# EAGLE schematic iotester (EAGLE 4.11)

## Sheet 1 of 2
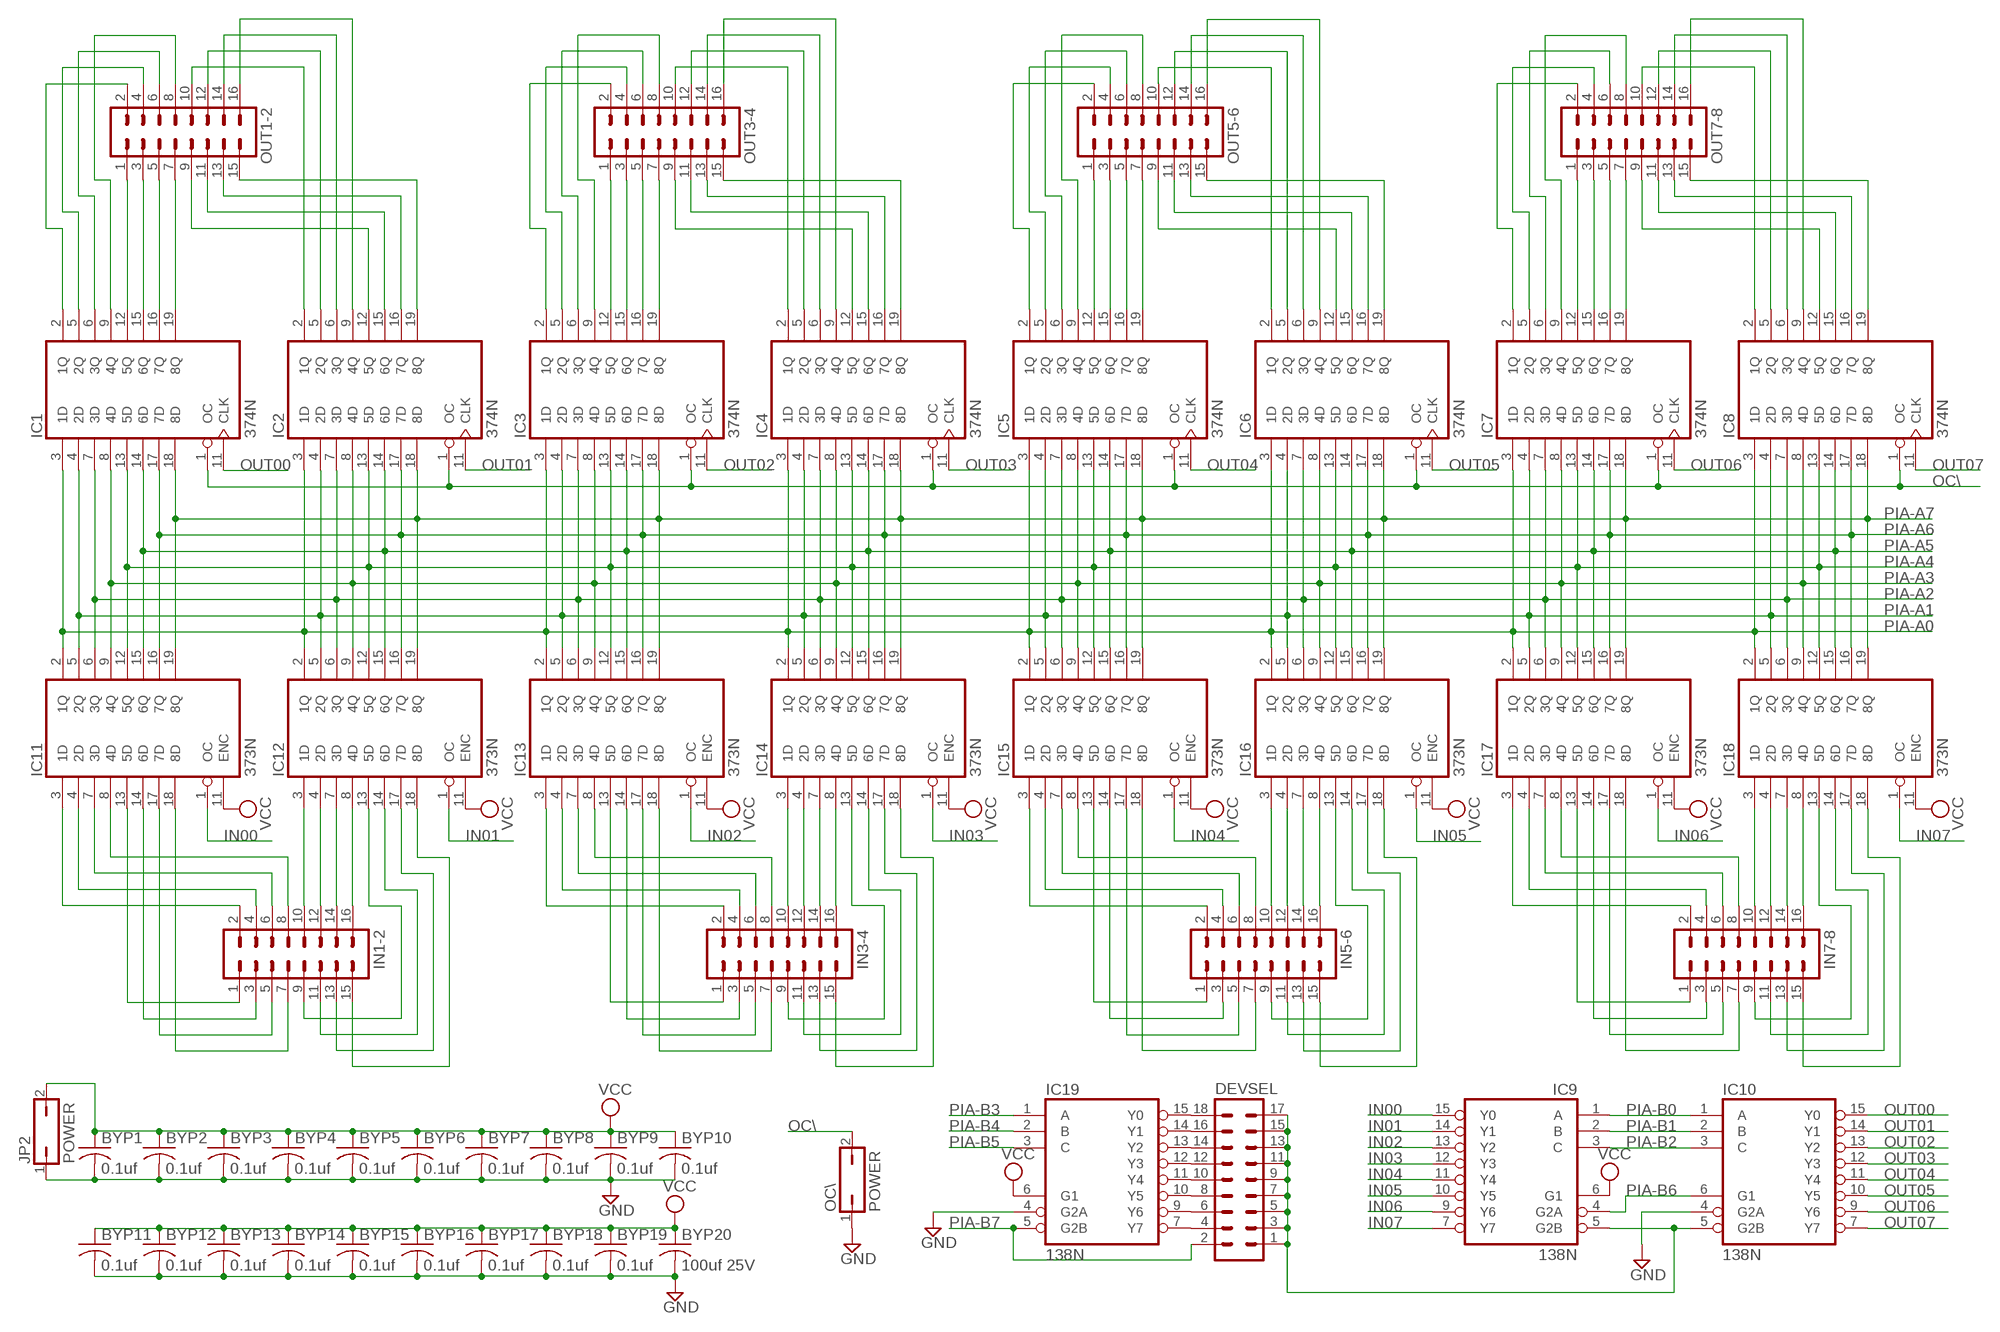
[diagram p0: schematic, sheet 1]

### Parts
BYP1  0.1uf  C-US050-025X075  [C050-025X075]
BYP2  0.1uf  C-US050-025X075  [C050-025X075]
BYP3  0.1uf  C-US050-025X075  [C050-025X075]
BYP4  0.1uf  C-US050-025X075  [C050-025X075]
BYP5  0.1uf  C-US050-025X075  [C050-025X075]
BYP6  0.1uf  C-US050-025X075  [C050-025X075]
BYP7  0.1uf  C-US050-025X075  [C050-025X075]
BYP8  0.1uf  C-US050-025X075  [C050-025X075]
BYP9  0.1uf  C-US050-025X075  [C050-025X075]
BYP10  0.1uf  C-US050-025X075  [C050-025X075]
BYP11  0.1uf  C-US050-025X075  [C050-025X075]
BYP12  0.1uf  C-US050-025X075  [C050-025X075]
BYP13  0.1uf  C-US050-025X075  [C050-025X075]
BYP14  0.1uf  C-US050-025X075  [C050-025X075]
BYP15  0.1uf  C-US050-025X075  [C050-025X075]
BYP16  0.1uf  C-US050-025X075  [C050-025X075]
BYP17  0.1uf  C-US050-025X075  [C050-025X075]
BYP18  0.1uf  C-US050-025X075  [C050-025X075]
BYP19  0.1uf  C-US050-025X075  [C050-025X075]
BYP20  100uf 25V  C-US150-064X183  [C150-064X183]
DEVSEL  MA09-2  [MA09-2]
IC1  374N  74LS374N  [DIL20]
IC2  374N  74LS374N  [DIL20]
IC3  374N  74LS374N  [DIL20]
IC4  374N  74LS374N  [DIL20]
IC5  374N  74LS374N  [DIL20]
IC6  374N  74LS374N  [DIL20]
IC7  374N  74LS374N  [DIL20]
IC8  374N  74LS374N  [DIL20]
IC9  138N  74LS138N  [DIL16]
IC10  138N  74LS138N  [DIL16]
IC11  373N  74LS373N  [DIL20]
IC12  373N  74LS373N  [DIL20]
IC13  373N  74LS373N  [DIL20]
IC14  373N  74LS373N  [DIL20]
IC15  373N  74LS373N  [DIL20]
IC16  373N  74LS373N  [DIL20]
IC17  373N  74LS373N  [DIL20]
IC18  373N  74LS373N  [DIL20]
IC19  138N  74LS138N  [DIL16]
IN1-2  MA08-2  [MA08-2]
IN3-4  MA08-2  [MA08-2]
IN5-6  MA08-2  [MA08-2]
IN7-8  MA08-2  [MA08-2]
JP2  POWER  JP1Q  [JP1]
OC\  POWER  JP1Q  [JP1]
OUT1-2  MA08-2  [MA08-2]
OUT3-4  MA08-2  [MA08-2]
OUT5-6  MA08-2  [MA08-2]
OUT7-8  MA08-2  [MA08-2]

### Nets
GND [Power]: BYP1.2 BYP2.2 BYP3.2 BYP4.2 BYP5.2 BYP6.2 BYP7.2 BYP8.2 BYP9.2 BYP10.2 BYP11.2 BYP12.2 BYP13.2 BYP14.2 BYP15.2 BYP16.2 BYP17.2 BYP18.2 BYP19.2 BYP20.2 IC10.4(G2A) IC19.4(G2A) JP2.1 OC\.1 ; also sheet 2
IN00: IC9.15(Y0) IC11.1(OC)
IN01: IC9.14(Y1) IC12.1(OC)
IN02: IC9.13(Y2) IC13.1(OC)
IN03: IC9.12(Y3) IC14.1(OC)
IN04: IC9.11(Y4) IC15.1(OC)
IN05: IC9.10(Y5) IC16.1(OC)
IN06: IC9.9(Y6) IC17.1(OC)
IN07: IC9.7(Y7) IC18.1(OC)
N$1: IC12.3(1D) IN1-2.10
N$2: IC12.4(2D) IN1-2.12
N$3: DEVSEL.18 IC19.15(Y0)
N$4: DEVSEL.16 IC19.14(Y1)
N$5: DEVSEL.14 IC19.13(Y2)
N$6: DEVSEL.12 IC19.12(Y3)
N$7: IC12.7(3D) IN1-2.14
N$8: IC12.8(4D) IN1-2.16
N$9: IC11.8(4D) IN1-2.8
N$10: IC11.7(3D) IN1-2.6
N$11: IC11.4(2D) IN1-2.4
N$12: IC11.3(1D) IN1-2.2
N$13: IC11.13(5D) IN1-2.1
N$14: IC11.14(6D) IN1-2.3
N$15: IC11.17(7D) IN1-2.5
N$16: IC11.18(8D) IN1-2.7
N$17: IC12.13(5D) IN1-2.9
N$18: IC12.14(6D) IN1-2.11
N$19: IC12.17(7D) IN1-2.13
N$20: IC12.18(8D) IN1-2.15
N$21: DEVSEL.10 IC19.11(Y4)
N$22: DEVSEL.8 IC19.10(Y5)
N$23: DEVSEL.6 IC19.9(Y6)
N$24: DEVSEL.4 IC19.7(Y7)
N$25: DEVSEL.1 DEVSEL.3 DEVSEL.5 DEVSEL.7 DEVSEL.9 DEVSEL.11 DEVSEL.13 DEVSEL.15 DEVSEL.17 IC9.5(G2B) IC10.5(G2B)
N$26: IC5.2(1Q) OUT5-6.2
N$27: IC18.8(4D) IN7-8.16
N$28: IC18.3(1D) IN7-8.10
N$29: IC14.3(1D) IN3-4.10
N$30: IC14.4(2D) IN3-4.12
N$31: IC14.7(3D) IN3-4.14
N$32: IC14.8(4D) IN3-4.16
N$33: IC3.12(5Q) OUT3-4.1
N$34: IC3.15(6Q) OUT3-4.3
N$35: IC3.16(7Q) OUT3-4.5
N$36: IC3.19(8Q) OUT3-4.7
N$37: IC13.3(1D) IN3-4.2
N$38: IC13.4(2D) IN3-4.4
N$39: IC13.7(3D) IN3-4.6
N$40: IC13.8(4D) IN3-4.8
N$41: IC14.13(5D) IN3-4.9
N$42: IC14.14(6D) IN3-4.11
N$43: IC14.17(7D) IN3-4.13
N$44: IC14.18(8D) IN3-4.15
N$45: IC13.13(5D) IN3-4.1
N$46: IC13.14(6D) IN3-4.3
N$47: IC13.17(7D) IN3-4.5
N$48: IC13.18(8D) IN3-4.7
N$49: IC3.5(2Q) OUT3-4.4
N$50: IC3.6(3Q) OUT3-4.6
N$51: IC3.2(1Q) OUT3-4.2
N$52: IC3.9(4Q) OUT3-4.8
N$53: IC1.12(5Q) OUT1-2.1
N$54: IC1.15(6Q) OUT1-2.3
N$55: IC1.16(7Q) OUT1-2.5
N$56: IC1.19(8Q) OUT1-2.7
N$57: IC1.2(1Q) OUT1-2.2
N$58: IC1.5(2Q) OUT1-2.4
N$59: IC1.6(3Q) OUT1-2.6
N$60: IC1.9(4Q) OUT1-2.8
N$61: IC2.19(8Q) OUT1-2.15
N$62: IC2.16(7Q) OUT1-2.13
N$63: IC2.15(6Q) OUT1-2.11
N$64: IC2.12(5Q) OUT1-2.9
N$65: IC2.2(1Q) OUT1-2.10
N$66: IC2.5(2Q) OUT1-2.12
N$67: IC2.6(3Q) OUT1-2.14
N$68: IC2.9(4Q) OUT1-2.16
N$69: IC4.2(1Q) OUT3-4.10
N$70: IC4.5(2Q) OUT3-4.12
N$71: IC4.6(3Q) OUT3-4.14
N$72: IC4.9(4Q) OUT3-4.16
N$73: IC4.19(8Q) OUT3-4.15
N$74: IC4.16(7Q) OUT3-4.13
N$75: IC4.15(6Q) OUT3-4.11
N$76: IC4.12(5Q) OUT3-4.9
N$77: IC16.3(1D) IN5-6.10
N$78: IC16.4(2D) IN5-6.12
N$79: IC16.7(3D) IN5-6.14
N$80: IC16.8(4D) IN5-6.16
N$81: IC5.12(5Q) OUT5-6.1
N$82: IC5.15(6Q) OUT5-6.3
N$83: IC5.16(7Q) OUT5-6.5
N$84: IC5.19(8Q) OUT5-6.7
N$85: IC7.12(5Q) OUT7-8.1
N$86: IC7.15(6Q) OUT7-8.3
N$87: IC7.16(7Q) OUT7-8.5
N$88: IC7.19(8Q) OUT7-8.7
N$89: IC5.5(2Q) OUT5-6.4
N$90: IC5.6(3Q) OUT5-6.6
N$91: IC5.9(4Q) OUT5-6.8
N$92: IC6.12(5Q) OUT5-6.9
N$93: IC6.15(6Q) OUT5-6.11
N$94: IC18.4(2D) IN7-8.12
N$95: IC6.16(7Q) OUT5-6.13
N$96: IC6.19(8Q) OUT5-6.15
N$97: IC6.2(1Q) OUT5-6.10
N$98: IC6.5(2Q) OUT5-6.12
N$99: IC6.6(3Q) OUT5-6.14
N$100: IC6.9(4Q) OUT5-6.16
N$101: IC15.3(1D) IN5-6.2
N$102: IC15.4(2D) IN5-6.4
N$103: IC15.7(3D) IN5-6.6
N$104: IC15.8(4D) IN5-6.8
N$105: IC16.13(5D) IN5-6.9
N$106: IC16.14(6D) IN5-6.11
N$107: IC16.17(7D) IN5-6.13
N$108: IC16.18(8D) IN5-6.15
N$109: IC15.13(5D) IN5-6.1
N$110: IC15.14(6D) IN5-6.3
N$111: IC15.17(7D) IN5-6.5
N$112: IC15.18(8D) IN5-6.7
N$113: IC8.19(8Q) OUT7-8.15
N$114: IC8.16(7Q) OUT7-8.13
N$115: IC8.15(6Q) OUT7-8.11
N$116: IC8.12(5Q) OUT7-8.9
N$117: IC8.2(1Q) OUT7-8.10
N$118: IC8.5(2Q) OUT7-8.12
N$119: IC8.6(3Q) OUT7-8.14
N$120: IC8.9(4Q) OUT7-8.16
N$121: IC7.9(4Q) OUT7-8.8
N$122: IC7.6(3Q) OUT7-8.6
N$123: IC7.5(2Q) OUT7-8.4
N$124: IC18.7(3D) IN7-8.14
N$125: IC18.13(5D) IN7-8.9
N$126: IC18.14(6D) IN7-8.11
N$127: IC18.17(7D) IN7-8.13
N$128: IC18.18(8D) IN7-8.15
N$129: IC17.3(1D) IN7-8.2
N$130: IC17.4(2D) IN7-8.4
N$131: IC17.7(3D) IN7-8.6
N$132: IC17.8(4D) IN7-8.8
N$133: IC17.13(5D) IN7-8.1
N$134: IC17.14(6D) IN7-8.3
N$135: IC17.17(7D) IN7-8.5
N$136: IC17.18(8D) IN7-8.7
N$137: IC7.2(1Q) OUT7-8.2
OC\: IC1.1(OC) IC2.1(OC) IC3.1(OC) IC4.1(OC) IC5.1(OC) IC6.1(OC) IC7.1(OC) IC8.1(OC) OC\.2
OUT00: IC1.11(CLK) IC10.15(Y0)
OUT01: IC2.11(CLK) IC10.14(Y1)
OUT02: IC3.11(CLK) IC10.13(Y2)
OUT03: IC4.11(CLK) IC10.12(Y3)
OUT04: IC5.11(CLK) IC10.11(Y4)
OUT05: IC6.11(CLK) IC10.10(Y5)
OUT06: IC7.11(CLK) IC10.9(Y6)
OUT07: IC8.11(CLK) IC10.7(Y7)
PIA-A0: IC1.3(1D) IC2.3(1D) IC3.3(1D) IC4.3(1D) IC5.3(1D) IC6.3(1D) IC7.3(1D) IC8.3(1D) IC11.2(1Q) IC12.2(1Q) IC13.2(1Q) IC14.2(1Q) IC15.2(1Q) IC16.2(1Q) IC17.2(1Q) IC18.2(1Q) ; also sheet 2
PIA-A1: IC1.4(2D) IC2.4(2D) IC3.4(2D) IC4.4(2D) IC5.4(2D) IC6.4(2D) IC7.4(2D) IC8.4(2D) IC11.5(2Q) IC12.5(2Q) IC13.5(2Q) IC14.5(2Q) IC15.5(2Q) IC16.5(2Q) IC17.5(2Q) IC18.5(2Q) ; also sheet 2
PIA-A2: IC1.7(3D) IC2.7(3D) IC3.7(3D) IC4.7(3D) IC5.7(3D) IC6.7(3D) IC7.7(3D) IC8.7(3D) IC11.6(3Q) IC12.6(3Q) IC13.6(3Q) IC14.6(3Q) IC15.6(3Q) IC16.6(3Q) IC17.6(3Q) IC18.6(3Q) ; also sheet 2
PIA-A3: IC1.8(4D) IC2.8(4D) IC3.8(4D) IC4.8(4D) IC5.8(4D) IC6.8(4D) IC7.8(4D) IC8.8(4D) IC11.9(4Q) IC12.9(4Q) IC13.9(4Q) IC14.9(4Q) IC15.9(4Q) IC16.9(4Q) IC17.9(4Q) IC18.9(4Q) ; also sheet 2
PIA-A4: IC1.13(5D) IC2.13(5D) IC3.13(5D) IC4.13(5D) IC5.13(5D) IC6.13(5D) IC7.13(5D) IC8.13(5D) IC11.12(5Q) IC12.12(5Q) IC13.12(5Q) IC14.12(5Q) IC15.12(5Q) IC16.12(5Q) IC17.12(5Q) IC18.12(5Q) ; also sheet 2
PIA-A5: IC1.14(6D) IC2.14(6D) IC3.14(6D) IC4.14(6D) IC5.14(6D) IC6.14(6D) IC7.14(6D) IC8.14(6D) IC11.15(6Q) IC12.15(6Q) IC13.15(6Q) IC14.15(6Q) IC15.15(6Q) IC16.15(6Q) IC17.15(6Q) IC18.15(6Q) ; also sheet 2
PIA-A6: IC1.17(7D) IC2.17(7D) IC3.17(7D) IC4.17(7D) IC5.17(7D) IC6.17(7D) IC7.17(7D) IC8.17(7D) IC11.16(7Q) IC12.16(7Q) IC13.16(7Q) IC14.16(7Q) IC15.16(7Q) IC16.16(7Q) IC17.16(7Q) IC18.16(7Q) ; also sheet 2
PIA-A7: IC1.18(8D) IC2.18(8D) IC3.18(8D) IC4.18(8D) IC5.18(8D) IC6.18(8D) IC7.18(8D) IC8.18(8D) IC11.19(8Q) IC12.19(8Q) IC13.19(8Q) IC14.19(8Q) IC15.19(8Q) IC16.19(8Q) IC17.19(8Q) IC18.19(8Q) ; also sheet 2
PIA-B0: IC9.1(A) IC10.1(A) ; also sheet 2
PIA-B1: IC9.2(B) IC10.2(B) ; also sheet 2
PIA-B2: IC9.3(C) IC10.3(C) ; also sheet 2
PIA-B3: IC19.1(A) ; also sheet 2
PIA-B4: IC19.2(B) ; also sheet 2
PIA-B5: IC19.3(C) ; also sheet 2
PIA-B6: IC9.4(G2A) IC10.6(G1) ; also sheet 2
PIA-B7: DEVSEL.2 IC19.5(G2B) ; also sheet 2
VCC [Power]: BYP1.1 BYP2.1 BYP3.1 BYP4.1 BYP5.1 BYP6.1 BYP7.1 BYP8.1 BYP9.1 BYP10.1 BYP11.1 BYP12.1 BYP13.1 BYP14.1 BYP15.1 BYP16.1 BYP17.1 BYP18.1 BYP19.1 BYP20.1 IC9.6(G1) IC11.11(ENC) IC12.11(ENC) IC13.11(ENC) IC14.11(ENC) IC15.11(ENC) IC16.11(ENC) IC17.11(ENC) IC18.11(ENC) IC19.6(G1) JP2.2 ; also sheet 2

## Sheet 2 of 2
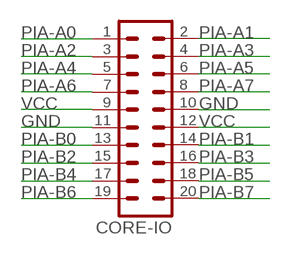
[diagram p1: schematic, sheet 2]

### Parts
CORE-IO  MA10-2  [MA10-2]

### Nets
GND [Power]: CORE-IO.10 CORE-IO.11 ; also sheet 1
PIA-A0: CORE-IO.1 ; also sheet 1
PIA-A1: CORE-IO.2 ; also sheet 1
PIA-A2: CORE-IO.3 ; also sheet 1
PIA-A3: CORE-IO.4 ; also sheet 1
PIA-A4: CORE-IO.5 ; also sheet 1
PIA-A5: CORE-IO.6 ; also sheet 1
PIA-A6: CORE-IO.7 ; also sheet 1
PIA-A7: CORE-IO.8 ; also sheet 1
PIA-B0: CORE-IO.13 ; also sheet 1
PIA-B1: CORE-IO.14 ; also sheet 1
PIA-B2: CORE-IO.15 ; also sheet 1
PIA-B3: CORE-IO.16 ; also sheet 1
PIA-B4: CORE-IO.17 ; also sheet 1
PIA-B5: CORE-IO.18 ; also sheet 1
PIA-B6: CORE-IO.19 ; also sheet 1
PIA-B7: CORE-IO.20 ; also sheet 1
VCC [Power]: CORE-IO.9 CORE-IO.12 ; also sheet 1

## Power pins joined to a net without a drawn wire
GND: IC1.10(GND) IC2.10(GND) IC3.10(GND) IC4.10(GND) IC5.10(GND) IC6.10(GND) IC7.10(GND) IC8.10(GND) IC9.8(GND) IC10.8(GND) IC11.10(GND) IC12.10(GND) IC13.10(GND) IC14.10(GND) IC15.10(GND) IC16.10(GND) IC17.10(GND) IC18.10(GND) IC19.8(GND)
VCC: IC1.20(VCC) IC2.20(VCC) IC3.20(VCC) IC4.20(VCC) IC5.20(VCC) IC6.20(VCC) IC7.20(VCC) IC8.20(VCC) IC9.16(VCC) IC10.16(VCC) IC11.20(VCC) IC12.20(VCC) IC13.20(VCC) IC14.20(VCC) IC15.20(VCC) IC16.20(VCC) IC17.20(VCC) IC18.20(VCC) IC19.16(VCC)

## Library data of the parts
BYP1-BYP20 = rcl:C-US: CAPACITOR, American symbol
CORE-IO = con-lstb:MA10-2: PIN HEADER
DEVSEL = con-lstb:MA09-2: PIN HEADER
IC1-IC8 = 74xx-us:74*374: Octal D type transparent LATCH, edge triggered
IC9 IC10 IC19 = 74xx-us:74*138: 3-line to 8-line DECODER/DEMULTIPLEXER
IC11-IC18 = 74xx-us:74*373: Octal D type transparent LATCH, edge triggered
IN1-2 IN3-4 IN5-6 IN7-8 OUT1-2 OUT3-4 OUT5-6 OUT7-8 = con-lstb:MA08-2: PIN HEADER
JP2 OC\ = jumper:JP1Q: JUMPER

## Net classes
1 Power: width 0.508 mm, drill 0.254 mm, clearance 0.254 mm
